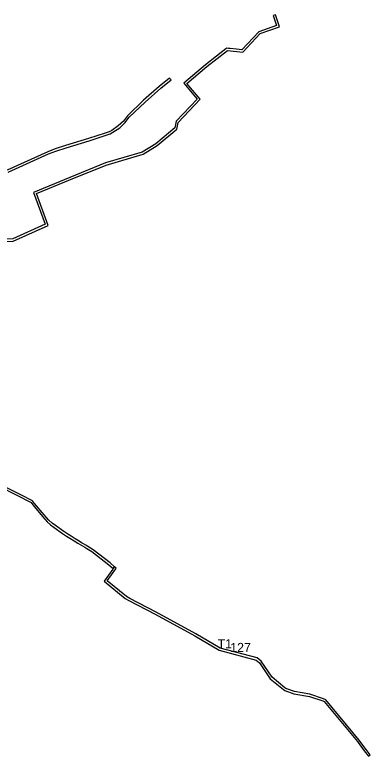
# Model space of a CAD drawing. Extents: x -477001 to -465642, y -1158278 to -1150672.
# Drawn here: x -469477 to -469015, y -1154129 to -1153166 of the extents above; entities that cross this region are included whole.
import ezdxf

# ---------------------------------------------------------------- set-up
doc = ezdxf.new("R2010")
doc.units = 0
for name, color, linetype in [('VPS_id', 7, 'Continuous'), ('VPS_n', 7, 'Continuous'), ('vyvlastneni_n', 7, 'Continuous')]:
    doc.layers.add(name, color=color, linetype=linetype)

msp = doc.modelspace()

# ---------------------------------------------------------------- linework, layer by layer
at = {"layer": 'VPS_n'}
for p, q in [((-469133.1, -1153181.56), (-469138.36, -1153165.97)), ((-469136.77, -1153180.05), (-469159.87, -1153187.86)), ((-469201.56, -1153209.3), (-469202.61, -1153210.12)), ((-469188.93, -1153210.71), (-469196.98, -1153209.81)), ((-469273.88, -1153250.52), (-469275.75, -1153248.18)), ((-469257.49, -1153254.96), (-469240.07, -1153275.46)), ((-469266.33, -1153314.55), (-469264.63, -1153305.77)), ((-469452.74, -1153396.65), (-469437.42, -1153438.18)), ((-469433.64, -1153439.78), (-469448.93, -1153398.33)), ((-469497.07, -1153779.12), (-469455.84, -1153799.88)), ((-469455.84, -1153799.88), (-469453.65, -1153802.74)), ((-469409.84, -1153843.26), (-469405.32, -1153846.15)), ((-469390.45, -1153851.92), (-469393.52, -1153850.12)), ((-469354.94, -1153880.65), (-469349.32, -1153885.43)), ((-469349.12, -1153885.59), (-469349.66, -1153886.34)), ((-469349.32, -1153885.43), (-469349.12, -1153885.59)), ((-469349.12, -1153885.59), (-469347.9, -1153883.88)), ((-469347.9, -1153883.88), (-469349.12, -1153885.59)), ((-469347.9, -1153883.88), (-469347.37, -1153883.14)), ((-469347.37, -1153883.14), (-469347.9, -1153883.88)), ((-469345.08, -1153885.09), (-469347.37, -1153883.14)), ((-469345.65, -1153885.89), (-469345.08, -1153885.09)), ((-469017.46, -1154129.38), (-469015.09, -1154127.54))]:
    msp.add_line(p, q, dxfattribs=at)
for points in [[(-469138.36, -1153165.97), (-469141.2, -1153166.93), (-469136.77, -1153180.05)], [(-469180.74, -1153214.64), (-469158.18, -1153190.44), (-469133.1, -1153181.56)], [(-469159.87, -1153187.86), (-469181.91, -1153211.49), (-469188.93, -1153210.71)], [(-469202.61, -1153210.12), (-469214.95, -1153219.77), (-469229.25, -1153230.96), (-469257.49, -1153254.96)], [(-469253.27, -1153255.3), (-469227.36, -1153233.28), (-469200.68, -1153212.42), (-469180.74, -1153214.64)], [(-469196.98, -1153209.81), (-469199.28, -1153209.56), (-469201.56, -1153209.3)], [(-469275.75, -1153248.18), (-469289.24, -1153258.95), (-469309.76, -1153277.05), (-469330.49, -1153297.04), (-469335.68, -1153303.96), (-469342.54, -1153310.27), (-469351.04, -1153316.11), (-469354.16, -1153317.82), (-469359.41, -1153319.73), (-469381.36, -1153326.77), (-469411.12, -1153335.98), (-469424.63, -1153340.33), (-469434.21, -1153343.98), (-469486.99, -1153367.69)], [(-469485.76, -1153370.43), (-469433.06, -1153346.75), (-469423.64, -1153343.16), (-469410.22, -1153338.84), (-469380.46, -1153329.63), (-469358.44, -1153322.57), (-469352.92, -1153320.56), (-469349.47, -1153318.67), (-469340.67, -1153312.62), (-469333.45, -1153305.98), (-469328.23, -1153299.03), (-469307.73, -1153279.26), (-469287.31, -1153261.25), (-469273.88, -1153250.52)], [(-469264.63, -1153305.77), (-469236.04, -1153275.56), (-469253.27, -1153255.3)], [(-469240.07, -1153275.46), (-469267.41, -1153304.35), (-469269.08, -1153312.94), (-469293.57, -1153333.5), (-469311.42, -1153344.34)], [(-469358.3, -1153361.17), (-469310.2, -1153347.11), (-469291.82, -1153335.95), (-469266.33, -1153314.55)], [(-469311.42, -1153344.34), (-469359.3, -1153358.34), (-469405.61, -1153377.39), (-469452.74, -1153396.65)], [(-469448.93, -1153398.33), (-469404.47, -1153380.16), (-469358.3, -1153361.17)], [(-469530.93, -1153466.4), (-469522.38, -1153461.1), (-469479.09, -1153460.16), (-469433.64, -1153439.78)], [(-469437.42, -1153438.18), (-469479.76, -1153457.17), (-469523.26, -1153458.12)], [(-469469.36, -1153789.71), (-469495.89, -1153776.35), (-469499.53, -1153775.07), (-469505.2, -1153773.71)], [(-469424.18, -1153829.8), (-469428.65, -1153826.37), (-469432.9, -1153822.64), (-469438.93, -1153815.92), (-469451.3, -1153800.88), (-469453.87, -1153797.51), (-469469.36, -1153789.71)], [(-469453.65, -1153802.74), (-469441.21, -1153817.88), (-469435.01, -1153824.78), (-469430.55, -1153828.69), (-469425.96, -1153832.22), (-469415.03, -1153839.95), (-469409.84, -1153843.26)], [(-469408.23, -1153840.73), (-469413.36, -1153837.46), (-469424.18, -1153829.8)], [(-469393.52, -1153850.12), (-469398.41, -1153847), (-469403.71, -1153843.62), (-469408.23, -1153840.73)], [(-469405.32, -1153846.15), (-469400.02, -1153849.53), (-469395.09, -1153852.68), (-469391.96, -1153854.51), (-469389.2, -1153856.12)], [(-469375.06, -1153861.14), (-469382.01, -1153856.91), (-469384.62, -1153855.32), (-469387.69, -1153853.53), (-469390.45, -1153851.92)], [(-469389.2, -1153856.12), (-469386.16, -1153857.9), (-469383.57, -1153859.47), (-469376.77, -1153863.61), (-469354.94, -1153880.65)], [(-469347.37, -1153883.14), (-469353.05, -1153878.32), (-469375.06, -1153861.14)], [(-469349.66, -1153886.34), (-469360.87, -1153902.04), (-469333.69, -1153924.36), (-469328.99, -1153926.96), (-469294.64, -1153945.02), (-469243.12, -1153973.17), (-469211.44, -1153991.71)], [(-469210.27, -1153988.91), (-469241.66, -1153970.55), (-469293.22, -1153942.38), (-469327.59, -1153924.31), (-469332.01, -1153921.86), (-469356.79, -1153901.48), (-469345.65, -1153885.89)], [(-469211.44, -1153991.71), (-469163.44, -1154004.43), (-469159.11, -1154007.87), (-469144.94, -1154028.7), (-469127.88, -1154042.87), (-469125.96, -1154044.2), (-469114.3, -1154048.29), (-469094.05, -1154051.64), (-469076.78, -1154057.42), (-469074.81, -1154058.48), (-469031.78, -1154110.48), (-469030.91, -1154111.64), (-469022.77, -1154122.54), (-469017.46, -1154129.38)], [(-469015.09, -1154127.54), (-469020.38, -1154120.72), (-469028.51, -1154109.84), (-469029.42, -1154108.62), (-469072.87, -1154056.12), (-469075.58, -1154054.66), (-469093.32, -1154048.72), (-469113.55, -1154045.37), (-469124.58, -1154041.5), (-469126.06, -1154040.48), (-469142.7, -1154026.66), (-469156.89, -1154005.81), (-469162.06, -1154001.69), (-469210.27, -1153988.91)]]:
    msp.add_lwpolyline(points, dxfattribs=at)
at = {"layer": 'vyvlastneni_n'}
for p, q in [((-469133.1, -1153181.56), (-469138.36, -1153165.97)), ((-469136.77, -1153180.05), (-469159.87, -1153187.86)), ((-469201.56, -1153209.3), (-469202.61, -1153210.12)), ((-469188.93, -1153210.71), (-469196.98, -1153209.81)), ((-469273.88, -1153250.52), (-469275.75, -1153248.18)), ((-469257.49, -1153254.96), (-469240.07, -1153275.46)), ((-469266.33, -1153314.55), (-469264.63, -1153305.77)), ((-469452.74, -1153396.65), (-469437.42, -1153438.18)), ((-469433.64, -1153439.78), (-469448.93, -1153398.33)), ((-469497.07, -1153779.12), (-469455.84, -1153799.88)), ((-469455.84, -1153799.88), (-469453.65, -1153802.74)), ((-469409.84, -1153843.26), (-469405.32, -1153846.15)), ((-469390.45, -1153851.92), (-469393.52, -1153850.12)), ((-469354.94, -1153880.65), (-469349.32, -1153885.43)), ((-469349.12, -1153885.59), (-469349.66, -1153886.34)), ((-469349.32, -1153885.43), (-469349.12, -1153885.59)), ((-469349.12, -1153885.59), (-469347.9, -1153883.88)), ((-469347.9, -1153883.88), (-469349.12, -1153885.59)), ((-469347.9, -1153883.88), (-469347.37, -1153883.14)), ((-469347.37, -1153883.14), (-469347.9, -1153883.88)), ((-469345.08, -1153885.09), (-469347.37, -1153883.14)), ((-469345.65, -1153885.89), (-469345.08, -1153885.09)), ((-469017.46, -1154129.38), (-469015.09, -1154127.54))]:
    msp.add_line(p, q, dxfattribs=at)
for points in [[(-469138.36, -1153165.97), (-469141.2, -1153166.93), (-469136.77, -1153180.05)], [(-469180.74, -1153214.64), (-469158.18, -1153190.44), (-469133.1, -1153181.56)], [(-469159.87, -1153187.86), (-469181.91, -1153211.49), (-469188.93, -1153210.71)], [(-469202.61, -1153210.12), (-469214.95, -1153219.77), (-469229.25, -1153230.96), (-469257.49, -1153254.96)], [(-469253.27, -1153255.3), (-469227.36, -1153233.28), (-469200.68, -1153212.42), (-469180.74, -1153214.64)], [(-469196.98, -1153209.81), (-469199.28, -1153209.56), (-469201.56, -1153209.3)], [(-469275.75, -1153248.18), (-469289.24, -1153258.95), (-469309.76, -1153277.05), (-469330.49, -1153297.04), (-469335.68, -1153303.96), (-469342.54, -1153310.27), (-469351.04, -1153316.11), (-469354.16, -1153317.82), (-469359.41, -1153319.73), (-469381.36, -1153326.77), (-469411.12, -1153335.98), (-469424.63, -1153340.33), (-469434.21, -1153343.98), (-469486.99, -1153367.69)], [(-469485.76, -1153370.43), (-469433.06, -1153346.75), (-469423.64, -1153343.16), (-469410.22, -1153338.84), (-469380.46, -1153329.63), (-469358.44, -1153322.57), (-469352.92, -1153320.56), (-469349.47, -1153318.67), (-469340.67, -1153312.62), (-469333.45, -1153305.98), (-469328.23, -1153299.03), (-469307.73, -1153279.26), (-469287.31, -1153261.25), (-469273.88, -1153250.52)], [(-469264.63, -1153305.77), (-469236.04, -1153275.56), (-469253.27, -1153255.3)], [(-469240.07, -1153275.46), (-469267.41, -1153304.35), (-469269.08, -1153312.94), (-469293.57, -1153333.5), (-469311.42, -1153344.34)], [(-469358.3, -1153361.17), (-469310.2, -1153347.11), (-469291.82, -1153335.95), (-469266.33, -1153314.55)], [(-469311.42, -1153344.34), (-469359.3, -1153358.34), (-469405.61, -1153377.39), (-469452.74, -1153396.65)], [(-469448.93, -1153398.33), (-469404.47, -1153380.16), (-469358.3, -1153361.17)], [(-469530.93, -1153466.4), (-469522.38, -1153461.1), (-469479.09, -1153460.16), (-469433.64, -1153439.78)], [(-469437.42, -1153438.18), (-469479.76, -1153457.17), (-469523.26, -1153458.12)], [(-469469.36, -1153789.71), (-469495.89, -1153776.35), (-469499.53, -1153775.07), (-469505.2, -1153773.71)], [(-469424.18, -1153829.8), (-469428.65, -1153826.37), (-469432.9, -1153822.64), (-469438.93, -1153815.92), (-469451.3, -1153800.88), (-469453.87, -1153797.51), (-469469.36, -1153789.71)], [(-469453.65, -1153802.74), (-469441.21, -1153817.88), (-469435.01, -1153824.78), (-469430.55, -1153828.69), (-469425.96, -1153832.22), (-469415.03, -1153839.95), (-469409.84, -1153843.26)], [(-469408.23, -1153840.73), (-469413.36, -1153837.46), (-469424.18, -1153829.8)], [(-469393.52, -1153850.12), (-469398.41, -1153847), (-469403.71, -1153843.62), (-469408.23, -1153840.73)], [(-469405.32, -1153846.15), (-469400.02, -1153849.53), (-469395.09, -1153852.68), (-469391.96, -1153854.51), (-469389.2, -1153856.12)], [(-469375.06, -1153861.14), (-469382.01, -1153856.91), (-469384.62, -1153855.32), (-469387.69, -1153853.53), (-469390.45, -1153851.92)], [(-469389.2, -1153856.12), (-469386.16, -1153857.9), (-469383.57, -1153859.47), (-469376.77, -1153863.61), (-469354.94, -1153880.65)], [(-469347.37, -1153883.14), (-469353.05, -1153878.32), (-469375.06, -1153861.14)], [(-469349.66, -1153886.34), (-469360.87, -1153902.04), (-469333.69, -1153924.36), (-469328.99, -1153926.96), (-469294.64, -1153945.02), (-469243.12, -1153973.17), (-469211.44, -1153991.71)], [(-469210.27, -1153988.91), (-469241.66, -1153970.55), (-469293.22, -1153942.38), (-469327.59, -1153924.31), (-469332.01, -1153921.86), (-469356.79, -1153901.48), (-469345.65, -1153885.89)], [(-469211.44, -1153991.71), (-469163.44, -1154004.43), (-469159.11, -1154007.87), (-469144.94, -1154028.7), (-469127.88, -1154042.87), (-469125.96, -1154044.2), (-469114.3, -1154048.29), (-469094.05, -1154051.64), (-469076.78, -1154057.42), (-469074.81, -1154058.48), (-469031.78, -1154110.48), (-469030.91, -1154111.64), (-469022.77, -1154122.54), (-469017.46, -1154129.38)], [(-469015.09, -1154127.54), (-469020.38, -1154120.72), (-469028.51, -1154109.84), (-469029.42, -1154108.62), (-469072.87, -1154056.12), (-469075.58, -1154054.66), (-469093.32, -1154048.72), (-469113.55, -1154045.37), (-469124.58, -1154041.5), (-469126.06, -1154040.48), (-469142.7, -1154026.66), (-469156.89, -1154005.81), (-469162.06, -1154001.69), (-469210.27, -1153988.91)]]:
    msp.add_lwpolyline(points, dxfattribs=at)

# ---------------------------------------------------------------- texts
at = {"layer": 'VPS_id'}
msp.add_text('127', height=12, dxfattribs=at).set_placement((-469196.95, -1153994.19))
at = {"layer": 'VPS_n'}
msp.add_text('T1', height=12, dxfattribs=at).set_placement((-469213.43, -1153989.38))

doc.saveas('drawing.dxf')
